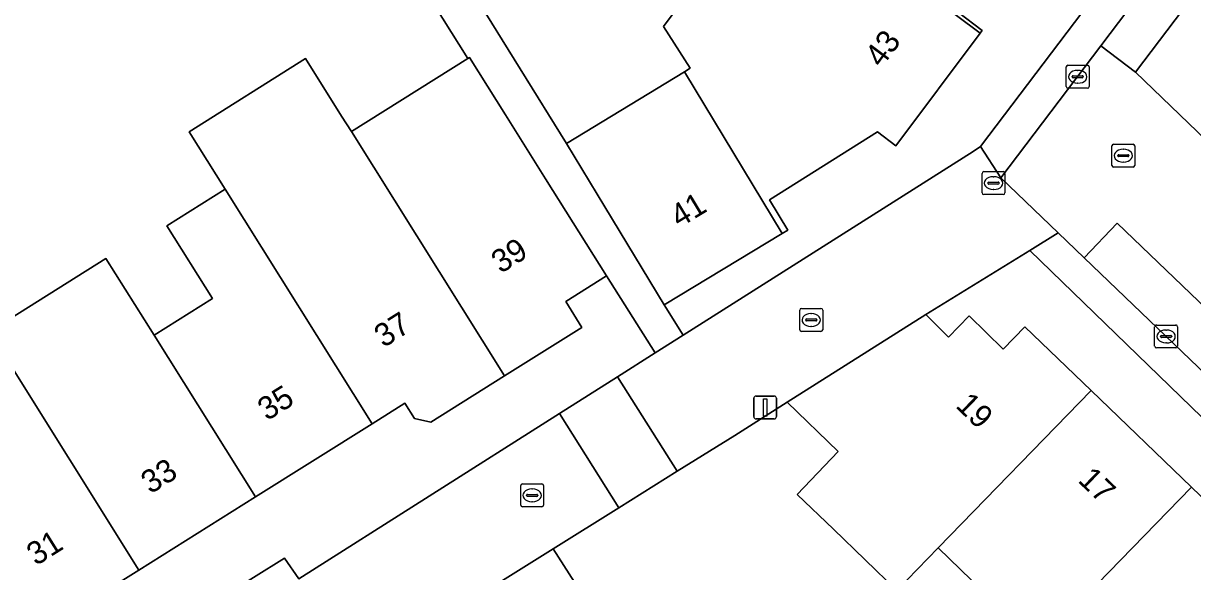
# Model space of a CAD drawing. Extents: x 157767 to 159172, y 387839 to 389425.
# Drawn here: x 158669.1 to 158720.1, y 388262.1 to 388286 of the extents above; entities that cross this region are included whole.
import ezdxf

# ---------------------------------------------------------------- set-up
doc = ezdxf.new("R2010")
doc.units = 0
for name, color, linetype in [('IMGEO_Brandkraan', 7, 'Continuous'), ('IMGEO_Erf', 7, 'Continuous'), ('IMGEO_Kolk', 7, 'Continuous'), ('IMGEO_Lichtmast', 7, 'Continuous'), ('IMGEO_Muur', 7, 'Continuous'), ('IMGEO_Pand', 7, 'Continuous'), ('IMGEO_Pand_nummerreeks', 7, 'Continuous'), ('IMGEO_Parkeervlak_open', 7, 'Continuous'), ('IMGEO_Rijbaan_lokaal_open', 7, 'Continuous'), ('IMGEO_Rioolput', 7, 'Continuous'), ('IMGEO_Voetpad_open', 7, 'Continuous')]:
    doc.layers.add(name, color=color, linetype=linetype)

msp = doc.modelspace()

# ---------------------------------------------------------------- linework, layer by layer
at = {"layer": 'IMGEO_Brandkraan'}
for p, q in [((158710.959, 388279.515), (158711.811, 388279.515)), ((158710.884, 388278.589), (158710.884, 388279.441)), ((158711.143, 388279.009), (158711.143, 388279.021)), ((158711.581, 388278.972), (158711.183, 388278.972)), ((158711.186, 388279.058), (158711.584, 388279.058)), ((158711.372, 388279.295), (158711.397, 388279.295)), ((158711.627, 388279.021), (158711.627, 388279.009)), ((158711.885, 388279.441), (158711.885, 388278.589)), ((158711.811, 388278.515), (158710.959, 388278.515)), ((158711.395, 388278.735), (158711.37, 388278.735))]:
    msp.add_line(p, q, dxfattribs=at)
for points in [[(158710.959, 388279.515), (158711.811, 388279.515)], [(158710.884, 388278.589), (158710.884, 388279.441)], [(158711.885, 388279.441), (158711.885, 388278.589)], [(158711.811, 388278.515), (158710.959, 388278.515)]]:
    msp.add_lwpolyline(points, dxfattribs=at)
for centre, radius, start, end in [((158710.961, 388279.439), 0.0765, 91.552, 178.448), ((158710.961, 388279.439), 0.0765, 91.552, 178.448), ((158711.809, 388279.439), 0.0765, 1.552, 88.448), ((158711.809, 388279.439), 0.0765, 1.552, 88.448), ((158711.183, 388279.018), 0.0403, 85.8775, 175.7526), ((158711.18, 388279.008), 0.0366, 178.938, 274.7102), ((158711.584, 388279.015), 0.043, 264.8664, 352.4533), ((158711.588, 388279.02), 0.0386, 1.7309, 96.639), ((158710.961, 388278.591), 0.0765, 181.552, 268.448), ((158710.961, 388278.591), 0.0765, 181.552, 268.448), ((158711.809, 388278.591), 0.0765, 271.552, 358.448), ((158711.809, 388278.591), 0.0765, 271.552, 358.448)]:
    msp.add_arc(centre, radius, start, end, dxfattribs=at)
for centre, major_axis, ratio, start_param, end_param in [((158711.371, 388279.015), (-0.387, 0.002), 0.722429, 4.712389, 7.853982), ((158711.396, 388279.015), (-0.39, 0.002), 0.717154, 1.570796, 4.712389)]:
    msp.add_ellipse(centre, major_axis=major_axis, ratio=ratio, start_param=start_param, end_param=end_param, dxfattribs=at)
at = {"layer": 'IMGEO_Erf'}
for points in [[(158709.851, 388286.453), (158710.888, 388285.678), (158710.802, 388285.562), (158707.127, 388280.646), (158706.321, 388281.249), (158701.61, 388278.292), (158702.414, 388276.965), (158702.166, 388276.815), (158697.019, 388273.699), (158697.851, 388272.386), (158710.495, 388280.401), (158710.822, 388280.608), (158727.632, 388302.796)], [(158667.578, 388272.536), (158672.666, 388275.727), (158674.767, 388272.378), (158677.311, 388273.975), (158675.316, 388277.156), (158677.859, 388278.751), (158676.288, 388281.256), (158681.369, 388284.444), (158682.944, 388281.941), (158683.37, 388281.264), (158688.453, 388284.454), (158682.611, 388293.765)], [(158684.666, 388293.785), (158692.751, 388280.75), (158697.898, 388283.867), (158698.155, 388284.022), (158696.992, 388285.852), (158701.803, 388292.289)], [(158660.15, 388250), (158680.456, 388262.662), (158681.074, 388261.752), (158692.444, 388268.959), (158694.978, 388270.565), (158696.628, 388271.611), (158694.501, 388274.966), (158692.723, 388273.851), (158693.432, 388272.722), (158690.055, 388270.603), (158686.842, 388268.588), (158686.126, 388268.752), (158685.707, 388269.421), (158684.274, 388268.522), (158679.187, 388265.331), (158674.099, 388262.139), (158669.013, 388258.948)], [(158713.333, 388258.87), (158708.973, 388263.107), (158707.162, 388261.243), (158704.401, 388263.926), (158702.813, 388265.434), (158704.614, 388267.304), (158702.383, 388269.453), (158700.104, 388268.007), (158697.588, 388266.448), (158695.044, 388264.857), (158692.172, 388263.06), (158694.97, 388258.704)]]:
    msp.add_lwpolyline(points, dxfattribs=at)
msp.add_lwpolyline([(158712.975, 388276.074), (158708.432, 388273.289), (158709.419, 388272.294), (158710.324, 388273.225), (158711.812, 388271.779), (158712.757, 388272.751), (158715.644, 388269.971), (158720.024, 388265.755), (158724.397, 388261.544), (158724.082, 388261.221), (158726.372, 388257.673), (158727.169, 388258.172), (158730.514, 388252.936), (158731.744, 388253.702), (158725.17, 388264.253)], close=True, dxfattribs=at)
at = {"layer": 'IMGEO_Kolk'}
for p, q in [((158714.558, 388283.228), (158714.558, 388284.08)), ((158714.633, 388284.154), (158715.485, 388284.154)), ((158715.559, 388284.08), (158715.559, 388283.228)), ((158714.817, 388283.648), (158714.817, 388283.66)), ((158715.255, 388283.611), (158714.857, 388283.611)), ((158714.86, 388283.697), (158715.258, 388283.697)), ((158715.046, 388283.934), (158715.071, 388283.934)), ((158715.301, 388283.66), (158715.301, 388283.648)), ((158715.485, 388283.154), (158714.633, 388283.154)), ((158715.069, 388283.374), (158715.044, 388283.374)), ((158702.932, 388272.621), (158702.932, 388273.473)), ((158703.007, 388273.547), (158703.859, 388273.547)), ((158703.933, 388273.473), (158703.933, 388272.621)), ((158703.191, 388273.041), (158703.191, 388273.053)), ((158703.629, 388273.004), (158703.231, 388273.004)), ((158703.234, 388273.09), (158703.632, 388273.09)), ((158703.42, 388273.327), (158703.445, 388273.327)), ((158703.675, 388273.053), (158703.675, 388273.041)), ((158703.859, 388272.547), (158703.007, 388272.547)), ((158703.443, 388272.767), (158703.418, 388272.767)), ((158718.416, 388271.9), (158718.416, 388272.752)), ((158718.491, 388272.826), (158719.343, 388272.826)), ((158718.675, 388272.32), (158718.675, 388272.332)), ((158718.718, 388272.369), (158719.116, 388272.369)), ((158718.904, 388272.606), (158718.929, 388272.606)), ((158719.159, 388272.332), (158719.159, 388272.32)), ((158719.417, 388272.752), (158719.417, 388271.9)), ((158719.343, 388271.826), (158718.491, 388271.826)), ((158719.113, 388272.283), (158718.715, 388272.283)), ((158718.927, 388272.046), (158718.902, 388272.046)), ((158690.758, 388264.969), (158690.758, 388265.821)), ((158690.833, 388265.895), (158691.685, 388265.895)), ((158691.759, 388265.821), (158691.759, 388264.969)), ((158691.017, 388265.389), (158691.017, 388265.401)), ((158691.455, 388265.352), (158691.057, 388265.352)), ((158691.06, 388265.438), (158691.458, 388265.438)), ((158691.246, 388265.675), (158691.271, 388265.675)), ((158691.501, 388265.401), (158691.501, 388265.389)), ((158691.685, 388264.895), (158690.833, 388264.895)), ((158691.269, 388265.115), (158691.244, 388265.115))]:
    msp.add_line(p, q, dxfattribs=at)
for points in [[(158714.558, 388283.228), (158714.558, 388284.08)], [(158714.633, 388284.154), (158715.485, 388284.154)], [(158715.559, 388284.08), (158715.559, 388283.228)], [(158715.485, 388283.154), (158714.633, 388283.154)], [(158702.932, 388272.621), (158702.932, 388273.473)], [(158703.007, 388273.547), (158703.859, 388273.547)], [(158703.933, 388273.473), (158703.933, 388272.621)], [(158703.859, 388272.547), (158703.007, 388272.547)], [(158718.416, 388271.9), (158718.416, 388272.752)], [(158718.491, 388272.826), (158719.343, 388272.826)], [(158719.417, 388272.752), (158719.417, 388271.9)], [(158719.343, 388271.826), (158718.491, 388271.826)], [(158690.758, 388264.969), (158690.758, 388265.821)], [(158690.833, 388265.895), (158691.685, 388265.895)], [(158691.759, 388265.821), (158691.759, 388264.969)], [(158691.685, 388264.895), (158690.833, 388264.895)]]:
    msp.add_lwpolyline(points, dxfattribs=at)
for centre, radius, start, end in [((158714.635, 388284.078), 0.0765, 91.552, 178.448), ((158714.635, 388284.078), 0.0765, 91.552, 178.448), ((158715.483, 388284.078), 0.0765, 1.552, 88.448), ((158715.483, 388284.078), 0.0765, 1.552, 88.448), ((158714.857, 388283.657), 0.0403, 85.8775, 175.7526), ((158714.854, 388283.647), 0.0366, 178.938, 274.7102), ((158715.258, 388283.654), 0.043, 264.8664, 352.4533), ((158715.262, 388283.659), 0.0386, 1.7309, 96.639), ((158714.635, 388283.23), 0.0765, 181.552, 268.448), ((158714.635, 388283.23), 0.0765, 181.552, 268.448), ((158715.483, 388283.23), 0.0765, 271.552, 358.448), ((158715.483, 388283.23), 0.0765, 271.552, 358.448), ((158703.009, 388273.471), 0.0765, 91.552, 178.448), ((158703.009, 388273.471), 0.0765, 91.552, 178.448), ((158703.857, 388273.471), 0.0765, 1.552, 88.448), ((158703.857, 388273.471), 0.0765, 1.552, 88.448), ((158703.231, 388273.05), 0.0403, 85.8775, 175.7526), ((158703.228, 388273.04), 0.0366, 178.938, 274.7102), ((158703.632, 388273.047), 0.043, 264.8664, 352.4533), ((158703.636, 388273.052), 0.0386, 1.7309, 96.639), ((158703.009, 388272.623), 0.0765, 181.552, 268.448), ((158703.009, 388272.623), 0.0765, 181.552, 268.448), ((158703.857, 388272.623), 0.0765, 271.552, 358.448), ((158703.857, 388272.623), 0.0765, 271.552, 358.448), ((158718.493, 388272.75), 0.0765, 91.552, 178.448), ((158718.493, 388272.75), 0.0765, 91.552, 178.448), ((158718.715, 388272.329), 0.0403, 85.8775, 175.7526), ((158718.712, 388272.319), 0.0366, 178.938, 274.7102), ((158719.116, 388272.326), 0.043, 264.8664, 352.4533), ((158719.12, 388272.331), 0.0386, 1.7309, 96.639), ((158719.341, 388272.75), 0.0765, 1.552, 88.448), ((158719.341, 388272.75), 0.0765, 1.552, 88.448), ((158718.493, 388271.902), 0.0765, 181.552, 268.448), ((158718.493, 388271.902), 0.0765, 181.552, 268.448), ((158719.341, 388271.902), 0.0765, 271.552, 358.448), ((158719.341, 388271.902), 0.0765, 271.552, 358.448), ((158690.835, 388265.819), 0.0765, 91.552, 178.448), ((158690.835, 388265.819), 0.0765, 91.552, 178.448), ((158691.683, 388265.819), 0.0765, 1.552, 88.448), ((158691.683, 388265.819), 0.0765, 1.552, 88.448), ((158691.057, 388265.398), 0.0403, 85.8775, 175.7526), ((158691.054, 388265.388), 0.0366, 178.938, 274.7102), ((158691.458, 388265.395), 0.043, 264.8664, 352.4533), ((158691.462, 388265.4), 0.0386, 1.7309, 96.639), ((158690.835, 388264.971), 0.0765, 181.552, 268.448), ((158690.835, 388264.971), 0.0765, 181.552, 268.448), ((158691.683, 388264.971), 0.0765, 271.552, 358.448), ((158691.683, 388264.971), 0.0765, 271.552, 358.448)]:
    msp.add_arc(centre, radius, start, end, dxfattribs=at)
for centre, major_axis, ratio, start_param, end_param in [((158715.045, 388283.654), (-0.387, 0.002), 0.722429, 4.712389, 7.853982), ((158715.07, 388283.654), (-0.39, 0.002), 0.717154, 1.570796, 4.712389), ((158703.419, 388273.047), (-0.387, 0.002), 0.722429, 4.712389, 7.853982), ((158703.444, 388273.047), (-0.39, 0.002), 0.717154, 1.570796, 4.712389), ((158718.903, 388272.326), (-0.387, 0.002), 0.722429, 4.712389, 7.853982), ((158718.928, 388272.326), (-0.39, 0.002), 0.717154, 1.570796, 4.712389), ((158691.245, 388265.395), (-0.387, 0.002), 0.722429, 4.712389, 7.853982), ((158691.27, 388265.395), (-0.39, 0.002), 0.717154, 1.570796, 4.712389)]:
    msp.add_ellipse(centre, major_axis=major_axis, ratio=ratio, start_param=start_param, end_param=end_param, dxfattribs=at)
at = {"layer": 'IMGEO_Lichtmast'}
for p, q in [((158700.925, 388268.829), (158700.925, 388269.629)), ((158700.925, 388269.629), (158700.925, 388268.829)), ((158701.025, 388269.729), (158701.815, 388269.729)), ((158701.815, 388269.729), (158701.025, 388269.729)), ((158701.915, 388269.629), (158701.915, 388268.829)), ((158701.915, 388268.829), (158701.915, 388269.629)), ((158701.815, 388268.729), (158701.025, 388268.729)), ((158701.025, 388268.729), (158701.815, 388268.729))]:
    msp.add_line(p, q, dxfattribs=at)
msp.add_lwpolyline([(158701.345, 388269.604), (158701.495, 388269.604), (158701.495, 388268.854), (158701.345, 388268.854), (158701.345, 388269.604)], dxfattribs=at)
for centre, start, end in [((158701.025, 388269.629), 90, 180), ((158701.025, 388269.629), 90, 180), ((158701.815, 388269.629), 0, 90), ((158701.815, 388269.629), 360, 90), ((158701.025, 388268.829), 180, 270), ((158701.025, 388268.829), 180, 270), ((158701.815, 388268.829), 270, 0), ((158701.815, 388268.829), 270, 0)]:
    msp.add_arc(centre, 0.1, start, end, dxfattribs=at)
at = {"layer": 'IMGEO_Muur'}
for points in [[(158702.383, 388269.453), (158700.104, 388268.007), (158697.588, 388266.448)], [(158697.588, 388266.448), (158695.044, 388264.857)], [(158695.044, 388264.857), (158692.172, 388263.06)]]:
    msp.add_lwpolyline(points, dxfattribs=at)
at = {"layer": 'IMGEO_Pand'}
for points in [[(158704.339, 388297.872), (158700.753, 388293.074), (158701.803, 388292.289), (158710.802, 388285.562), (158710.888, 388285.678), (158709.851, 388286.453), (158713.351, 388291.136)], [(158710.802, 388285.562), (158701.803, 388292.289), (158696.992, 388285.852), (158698.155, 388284.022), (158697.898, 388283.867), (158702.166, 388276.815), (158702.414, 388276.965), (158701.61, 388278.292), (158706.321, 388281.249), (158707.127, 388280.646)], [(158683.37, 388281.264), (158682.944, 388281.941), (158681.369, 388284.444), (158676.288, 388281.256), (158677.859, 388278.751), (158684.274, 388268.522), (158685.707, 388269.421), (158686.126, 388268.752), (158686.842, 388268.588), (158690.055, 388270.603)], [(158691.844, 388279.201), (158690.093, 388281.993), (158688.522, 388284.497), (158688.453, 388284.454), (158683.37, 388281.264), (158690.055, 388270.603), (158693.432, 388272.722), (158692.723, 388273.851), (158694.501, 388274.966)], [(158697.898, 388283.867), (158692.751, 388280.75), (158694.43, 388277.977), (158697.019, 388273.699), (158702.166, 388276.815)], [(158679.187, 388265.331), (158684.274, 388268.522), (158677.859, 388278.751), (158675.316, 388277.156), (158677.311, 388273.975), (158674.767, 388272.378)], [(158679.187, 388265.331), (158674.767, 388272.378), (158672.666, 388275.727), (158667.578, 388272.536), (158667.998, 388271.867), (158674.099, 388262.139)], [(158715.644, 388269.971), (158712.757, 388272.751), (158711.812, 388271.779), (158710.324, 388273.225), (158709.419, 388272.294), (158708.432, 388273.289), (158702.383, 388269.453), (158704.614, 388267.304), (158702.813, 388265.434), (158704.401, 388263.926), (158707.162, 388261.243), (158708.973, 388263.107)], [(158669.013, 388258.948), (158674.099, 388262.139), (158667.998, 388271.867), (158662.912, 388268.676)], [(158715.644, 388269.971), (158708.973, 388263.107), (158713.333, 388258.87), (158720.024, 388265.755)], [(158713.333, 388258.87), (158713.441, 388258.765), (158712.249, 388257.538), (158716.771, 388251.529), (158726.372, 388257.673), (158724.082, 388261.221), (158724.397, 388261.544), (158720.024, 388265.755)]]:
    msp.add_lwpolyline(points, close=True, dxfattribs=at)
at = {"layer": 'IMGEO_Parkeervlak_open'}
for points in [[(158726.72, 388299.082), (158716.063, 388284.997), (158717.582, 388283.848), (158728.24, 388297.933)], [(158724.583, 388266.886), (158726.034, 388268.399), (158716.781, 388277.271), (158715.334, 388275.761)]]:
    msp.add_lwpolyline(points, close=True, dxfattribs=at)
at = {"layer": 'IMGEO_Rijbaan_lokaal_open'}
for points in [[(158735.176, 388298.609), (158736.503, 388299.956), (158734.853, 388301.572), (158734.137, 388302.623), (158730.147, 388309.07), (158726.11, 388306.571), (158728.941, 388302.017), (158726.72, 388299.082), (158728.24, 388297.933), (158717.582, 388283.848), (158723.372, 388278.281)], [(158781.651, 388185.725), (158781.298, 388186.286), (158773.917, 388198.04), (158767.195, 388208.702), (158754.82, 388228.502), (158750.346, 388235.683), (158749.699, 388236.721), (158747, 388241.052), (158741.436, 388250), (158729.583, 388268.931), (158723.372, 388278.281), (158717.582, 388283.848), (158716.063, 388284.997), (158711.707, 388279.239), (158714.205, 388276.844), (158715.334, 388275.761), (158716.781, 388277.271), (158726.034, 388268.399), (158724.583, 388266.886)], [(158673.038, 388249.699), (158673.529, 388250), (158679.282, 388253.53), (158684.888, 388256.968), (158684.197, 388258.07), (158692.172, 388263.06), (158695.044, 388264.857), (158692.444, 388268.959), (158681.074, 388261.752), (158680.456, 388262.662), (158660.15, 388250)], [(158694.97, 388258.704), (158692.172, 388263.06), (158684.197, 388258.07)]]:
    msp.add_lwpolyline(points, dxfattribs=at)
for points in [[(158712.975, 388276.074), (158714.205, 388276.844), (158711.707, 388279.239), (158710.822, 388280.608), (158710.495, 388280.401), (158697.851, 388272.386), (158696.628, 388271.611), (158694.978, 388270.565), (158697.588, 388266.448), (158700.104, 388268.007), (158702.383, 388269.453), (158708.432, 388273.289)], [(158697.588, 388266.448), (158694.978, 388270.565), (158692.444, 388268.959), (158695.044, 388264.857)]]:
    msp.add_lwpolyline(points, close=True, dxfattribs=at)
at = {"layer": 'IMGEO_Rioolput'}
for p, q in [((158716.549, 388279.786), (158716.549, 388280.638)), ((158716.624, 388280.712), (158717.476, 388280.712)), ((158717.037, 388280.492), (158717.062, 388280.492)), ((158717.55, 388280.638), (158717.55, 388279.786)), ((158716.808, 388280.206), (158716.808, 388280.218)), ((158717.246, 388280.169), (158716.848, 388280.169)), ((158716.851, 388280.255), (158717.249, 388280.255)), ((158717.292, 388280.218), (158717.292, 388280.206)), ((158717.476, 388279.712), (158716.624, 388279.712)), ((158717.06, 388279.932), (158717.035, 388279.932))]:
    msp.add_line(p, q, dxfattribs=at)
for points in [[(158716.549, 388279.786), (158716.549, 388280.638)], [(158716.624, 388280.712), (158717.476, 388280.712)], [(158717.55, 388280.638), (158717.55, 388279.786)], [(158717.476, 388279.712), (158716.624, 388279.712)]]:
    msp.add_lwpolyline(points, dxfattribs=at)
for centre, radius, start, end in [((158716.626, 388280.636), 0.0765, 91.552, 178.448), ((158716.626, 388280.636), 0.0765, 91.552, 178.448), ((158717.474, 388280.636), 0.0765, 1.552, 88.448), ((158717.474, 388280.636), 0.0765, 1.552, 88.448), ((158716.848, 388280.215), 0.0403, 85.8775, 175.7526), ((158716.845, 388280.205), 0.0366, 178.938, 274.7102), ((158717.249, 388280.212), 0.043, 264.8664, 352.4533), ((158717.253, 388280.217), 0.0386, 1.7309, 96.639), ((158716.626, 388279.788), 0.0765, 181.552, 268.448), ((158716.626, 388279.788), 0.0765, 181.552, 268.448), ((158717.474, 388279.788), 0.0765, 271.552, 358.448), ((158717.474, 388279.788), 0.0765, 271.552, 358.448)]:
    msp.add_arc(centre, radius, start, end, dxfattribs=at)
for centre, major_axis, ratio, start_param, end_param in [((158717.036, 388280.212), (-0.387, 0.002), 0.722429, 4.712389, 7.853982), ((158717.061, 388280.212), (-0.39, 0.002), 0.717154, 1.570796, 4.712389)]:
    msp.add_ellipse(centre, major_axis=major_axis, ratio=ratio, start_param=start_param, end_param=end_param, dxfattribs=at)
at = {"layer": 'IMGEO_Voetpad_open'}
for points in [[(158695.013, 388355.305), (158698.377, 388349.906), (158699.757, 388347.691), (158708.677, 388333.375), (158707.851, 388332.826), (158709.575, 388330.031), (158711.419, 388327.042), (158713.347, 388323.904), (158715.228, 388320.899), (158716.055, 388321.427), (158722.916, 388310.385), (158727.632, 388302.796), (158710.822, 388280.608), (158711.707, 388279.239), (158716.063, 388284.997), (158726.72, 388299.082), (158728.941, 388302.017), (158726.11, 388306.571), (158724.452, 388309.238), (158706.34, 388338.368)], [(158724.583, 388266.886), (158715.334, 388275.761), (158714.205, 388276.844), (158712.975, 388276.074), (158725.17, 388264.253), (158731.744, 388253.702), (158732.567, 388252.38), (158734.05, 388250), (158752.874, 388219.788), (158754.146, 388220.596), (158749.112, 388228.601), (158735.718, 388250)]]:
    msp.add_lwpolyline(points, dxfattribs=at)
msp.add_lwpolyline([(158684.666, 388293.785), (158680.986, 388299.727), (158679.542, 388298.894), (158682.718, 388293.832), (158682.611, 388293.765), (158688.453, 388284.454), (158688.522, 388284.497), (158690.093, 388281.993), (158691.844, 388279.201), (158694.501, 388274.966), (158696.628, 388271.611), (158697.851, 388272.386), (158697.019, 388273.699), (158694.43, 388277.977), (158692.751, 388280.75)], close=True, dxfattribs=at)

# ---------------------------------------------------------------- texts
at = {"layer": 'IMGEO_Pand_nummerreeks'}
for s, rotation, p in [('43', 53.2278, (158706.495, 388284.009)), ('41', 31.1908, (158697.678, 388277.044)), ('39', 32.0914, (158689.885, 388275.047)), ('37', 32.1028, (158684.778, 388271.814)), ('35', 32.1021, (158679.691, 388268.622)), ('19', 315.8192, (158709.692, 388269.266)), ('33', 32.1021, (158674.604, 388265.431)), ('17', 316.093, (158715.03, 388266.01)), ('31', 32.1021, (158669.613, 388262.299))]:
    msp.add_text(s, height=1, rotation=rotation, dxfattribs=at).set_placement(p)

doc.saveas('drawing.dxf')
